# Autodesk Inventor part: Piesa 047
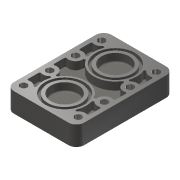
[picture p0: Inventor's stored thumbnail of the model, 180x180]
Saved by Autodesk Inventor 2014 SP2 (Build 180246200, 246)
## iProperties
Created: 2009-01
Part Number: Piesa 047
Document SubType Name: Modeling
Designer: Costel
Material: Steel, Cast
Density: 7.85 g/cm^3
Appearance: Steel - Cast
Author: Costel
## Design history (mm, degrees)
sketch "Sketch1"
  geometry: L1 (0, -154.971)-(0, 206.627) reference; L2 (-112.971, 0)-(150.627, 0) reference; L3 (-70, 125)-(70, 125); L4 (90, 105)-(90, -105); L5 (70, -125)-(-70, -125); L6 (-90, -105)-(-90, 105); A1 r 20 centre (-70, 105) between (-70, 125) and (-90, 105); A2 r 20 centre (70, 105) between (90, 105) and (70, 125); A3 r 20 centre (70, -105) between (70, -125) and (90, -105); A4 r 20 centre (-70, -105) between (-90, -105) and (-70, -125); 3 further points
  constraints: 8 end point, 8 point on circle, 8 tangent, 6 point on line, 4 centre point, 3 equal radius, 2 parallel, 1 horizontal, 1 perpendicular, 2 other
  dimensions: "d0" = 250 distance of point (-90, -125) point (-90, 125); "d1" = 180 distance of point (-90, 125) point (90, 125); "d2" = 20 radius of A1
extrude "Extrusion1" new body sketch "Sketch1" distance "d3" = 50; taper "d4" = 0 deg
sketch "Sketch2"
  geometry: L1 (0, -150)-(0, 200) reference; L2 (108, 0)-(-144, 0) reference; L3 (-70, -154.971)-(-70, 206.627); L4 (112.971, 33)-(-150.627, 33); L5 (112.971, 100)-(-150.627, 100); 8 further points
  constraints: 6 end point, 6 symmetric about line, 4 point on line, 3 parallel
  dimensions: "d6" = 33 distance between parallel lines of L4 L2; "d7" = 67 distance between parallel lines of L4 L5; "d8" = 70 distance between parallel lines of L1 L3
hole "Hole1" sketch "Sketch2" at (-70, 100), (-70, 33), (70, 100), (70, 33), (-70, -100), (70, -100), (70, -33), (-70, -33) diameter "d9" = 18; stored, may be unused: countersink angle "d13" = 90 deg, drill point angle "d15" = 118 deg; dims "d10" = 6, "d11" = 25, "d12" = 35, "d14" = 8
sketch "Sketch3"
  geometry: L1 (-108, 0)-(144, 0) reference; L2 (0, -150)-(0, 200) reference; L3 (-79, 79.875)-(-79, 53.125); L4 (79, 79.875)-(79, 53.125); L5 (-79, -79.875)-(-79, -53.125); L6 (79, -79.875)-(79, -53.125); L7 (-79, 12.875)-(-79, -12.875); L8 (79, 12.875)-(79, -12.875); C1 r 9 at (-70, 100) reference; C2 r 9 at (70, 33) reference; C3 r 9 at (-70, 33) reference; C4 r 9 at (-70, -100) reference; A1 r 18 centre (-70, 100) between (-75.143, 82.75) and (-56.136, 88.52); A2 r 18 centre (-70, 33) between (-57.584, 46.033) and (-75.143, 50.25); A3 r 55 centre (0, 65) between (-51.041, 85.489) and (-52.644, 49.074); A4 r 3 centre (-76, 53.125) between (-79, 53.125) and (-75.143, 50.25); A5 r 3 centre (-76, 79.875) between (-75.143, 82.75) and (-79, 79.875); A6 r 3 centre (-53.825, 86.607) between (-51.041, 85.489) and (-56.136, 88.52); A7 r 3 centre (-55.515, 48.205) between (-57.584, 46.033) and (-52.644, 49.074); A8 r 3 centre (53.825, 86.607) between (56.136, 88.52) and (51.041, 85.489); A9 r 3 centre (55.515, 48.205) between (52.644, 49.074) and (57.584, 46.033); A10 r 18 centre (70, 100) between (56.136, 88.52) and (75.143, 82.75); A11 r 18 centre (70, 33) between (75.143, 50.25) and (57.584, 46.033); A12 r 3 centre (76, 53.125) between (75.143, 50.25) and (79, 53.125); A13 r 3 centre (76, 79.875) between (79, 79.875) and (75.143, 82.75); A14 r 55 centre (0, 65) between (-51.041, 85.489) and (-52.644, 49.074); A15 r 55 centre (0, 65) between (52.644, 49.074) and (51.041, 85.489); A16 r 3 centre (-55.515, -48.205) between (-52.644, -49.074) and (-57.584, -46.033); A17 r 18 centre (-70, -33) between (-75.143, -50.25) and (-57.584, -46.033); A18 r 3 centre (-76, -53.125) between (-75.143, -50.25) and (-79, -53.125); A19 r 3 centre (-76, -79.875) between (-79, -79.875) and (-75.143, -82.75); A20 r 55 centre (0, -65) between (-52.644, -49.074) and (-51.041, -85.489); A21 r 18 centre (-70, -100) between (-56.136, -88.52) and (-75.143, -82.75); A22 r 3 centre (-53.825, -86.607) between (-56.136, -88.52) and (-51.041, -85.489); A23 r 55 centre (0, -65) between (-52.644, -49.074) and (-51.041, -85.489); A24 r 55 centre (0, -65) between (51.041, -85.489) and (52.644, -49.074); A25 r 3 centre (53.825, -86.607) between (51.041, -85.489) and (56.136, -88.52); A26 r 3 centre (55.515, -48.205) between (57.584, -46.033) and (52.644, -49.074); A27 r 18 centre (70, -100) between (75.143, -82.75) and (56.136, -88.52); A28 r 18 centre (70, -33) between (57.584, -46.033) and (75.143, -50.25); A29 r 3 centre (76, -53.125) between (79, -53.125) and (75.143, -50.25); A30 r 3 centre (76, -79.875) between (75.143, -82.75) and (79, -79.875); A31 r 55 centre (0, -65) between (-52.644, -49.074) and (-51.041, -85.489); A32 r 55 centre (0, -65) between (51.041, -85.489) and (52.644, -49.074); A33 r 3 centre (-49.024, 34.006) between (-46.488, 35.609) and (-52.021, 33.862); A34 r 3 centre (49.024, 34.006) between (52.021, 33.862) and (46.488, 35.609); A35 r 55 centre (0, 65) between (-46.488, 35.609) and (46.488, 35.609); A36 r 18 centre (-70, 33) between (-57.584, 46.033) and (-75.143, 50.25); A37 r 18 centre (-70, 33) between (-75.143, 15.75) and (-52.021, 33.862); A38 r 18 centre (70, 33) between (52.021, 33.862) and (75.143, 15.75); A39 r 18 centre (70, 33) between (75.143, 50.25) and (57.584, 46.033); A40 r 55 centre (0, 65) between (52.644, 49.074) and (51.041, 85.489); A41 r 55 centre (0, 65) between (-51.041, 85.489) and (-52.644, 49.074); A42 r 3 centre (-49.024, -34.006) between (-52.021, -33.862) and (-46.488, -35.609); A43 r 3 centre (49.024, -34.006) between (46.488, -35.609) and (52.021, -33.862); A44 r 18 centre (-70, -33) between (-52.021, -33.862) and (-75.143, -15.75); A45 r 18 centre (-70, -33) between (-75.143, -50.25) and (-57.584, -46.033); A46 r 55 centre (0, -65) between (46.488, -35.609) and (-46.488, -35.609); A47 r 55 centre (0, -65) between (-52.644, -49.074) and (-51.041, -85.489); A48 r 55 centre (0, -65) between (51.041, -85.489) and (52.644, -49.074); A49 r 18 centre (70, -33) between (57.584, -46.033) and (75.143, -50.25); A50 r 18 centre (70, -33) between (75.143, -15.75) and (52.021, -33.862); A51 r 3 centre (-76, 12.875) between (-75.143, 15.75) and (-79, 12.875); A52 r 3 centre (-76, -12.875) between (-79, -12.875) and (-75.143, -15.75); A53 r 3 centre (76, -12.875) between (75.143, -15.75) and (79, -12.875); A54 r 3 centre (76, 12.875) between (79, 12.875) and (75.143, 15.75); 2 further points
  constraints: 108 point on circle, 56 symmetric about line, 54 centre point, 23 tangent, 12 end point, 11 coincident, 7 equal radius, 2 parallel, 1 perpendicular, 1 point on line, 24 other
  dimensions: "d17" = 130 distance of A3.centre A31.centre; "d20" = 3 radius of A4; "d21" = 55 radius of A3; "d23" = 18 radius of A1; "d24" = 3 radius of A6; "d25" = 3 radius of A51
extrude "Extrusion2" cut sketch "Sketch3" distance "d26" = 20; taper "d27" = 0 deg
sketch "Sketch4"
  geometry: L1 (-108, 0)-(144, 0) reference; L2 (0, -150)-(0, 200) reference; C1 r 35 at (0, -65); C2 r 43 at (0, -65); C3 r 50 at (0, -65); C4 r 50 at (0, 65); C5 r 43 at (0, 65); C6 r 35 at (0, 65); A1 r 55 centre (0, -65) between (51.041, -85.489) and (52.644, -49.074) reference
  constraints: 6 centre point, 5 coincident, 3 symmetric about line, 3 other
  dimensions: "d28" = 70 diameter of C1; "d29" = 86 diameter of C2; "d30" = 100 diameter of C3
extrude "Extrusion4" cut sketch "Sketch4" distance "d36" = 20; taper "d37" = 0 deg
sketch "Sketch5"
  geometry: L1 (-112.971, 0)-(150.627, 0) reference; C1 r 43 at (0, -65); C2 r 50 at (0, -65); C3 r 50 at (0, 65); C4 r 43 at (0, 65); A1 r 55 centre (0, -65) between (51.041, -85.489) and (52.644, -49.074) reference
  constraints: 4 centre point, 3 coincident, 2 symmetric about line, 2 other
  dimensions: "d38" = 100 diameter of C2; "d39" = 86 diameter of C1
extrude "Extrusion5" cut sketch "Sketch5" distance "d40" = 10; taper "d41" = 0 deg
fillet "Fillet1" dims "d42" = 3
body "Solid1"
other parameters: "d19" = 11
